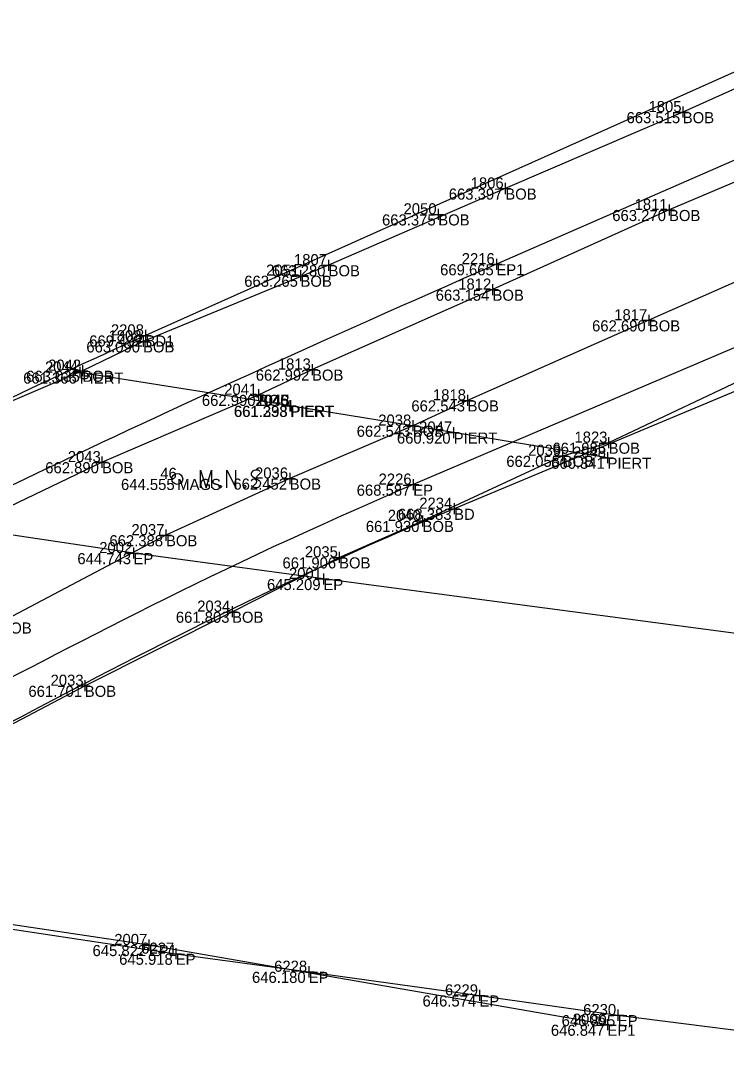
# Model space of a CAD drawing. Extents: x 2197382 to 2204062, y 634117 to 636522.
# Drawn here: x 2202884.1 to 2202947.7, y 635326 to 635420.1 of the extents above; entities that cross this region are included whole.
import ezdxf

# ---------------------------------------------------------------- set-up
doc = ezdxf.new("R2010")
doc.units = 0
for name, color, linetype in [('_CIVIL_CONSTRUCTION', 7, 'Continuous'), ('BR_X_SV_Bottom_of_Beam', 7, 'Continuous'), ('BR_X_SV_Bottom_of_Beam_Text', 7, 'Continuous'), ('BR_X_SV_Deck_Top', 7, 'Continuous'), ('BR_X_SV_Deck_Top_Text', 7, 'Continuous'), ('BR_X_SV_Pier', 7, 'Continuous'), ('BR_X_SV_Pier_Cap_Top_Text', 7, 'Continuous'), ('GE_P_Alignment_100_Distances', 7, 'Continuous'), ('SH_Border', 7, 'Continuous'), ('SH_Cut_Line', 7, 'Continuous'), ('SH_Data', 7, 'Continuous'), ('SV_P_Control_Cells_Set', 7, 'Continuous')]:
    doc.layers.add(name, color=color, linetype=linetype)

msp = doc.modelspace()

# ---------------------------------------------------------------- linework, layer by layer
at = {"layer": '_CIVIL_CONSTRUCTION'}
for p, q in [((2202943.796, 635412.429), (2202943.796, 635411.429)), ((2202943.296, 635411.929), (2202944.296, 635411.929)), ((2202943.796, 635411.929), (2202943.796, 635411.929)), ((2202927.298, 635405.044), (2202928.298, 635405.044)), ((2202927.798, 635405.544), (2202927.798, 635404.544)), ((2202927.798, 635405.044), (2202927.798, 635405.044)), ((2202921.756, 635403.216), (2202921.756, 635402.216)), ((2202942.056, 635403.113), (2202943.056, 635403.113)), ((2202942.556, 635403.613), (2202942.556, 635402.613)), ((2202942.556, 635403.113), (2202942.556, 635403.113)), ((2202921.256, 635402.716), (2202922.256, 635402.716)), ((2202921.756, 635402.716), (2202921.756, 635402.716)), ((2202911.366, 635398.135), (2202912.366, 635398.135)), ((2202911.866, 635398.635), (2202911.866, 635397.635)), ((2202911.866, 635398.135), (2202911.866, 635398.135)), ((2202926.493, 635398.223), (2202927.493, 635398.223)), ((2202926.993, 635398.723), (2202926.993, 635397.723)), ((2202926.993, 635398.223), (2202926.993, 635398.223)), ((2202908.837, 635397.193), (2202909.837, 635397.193)), ((2202909.337, 635397.693), (2202909.337, 635396.693)), ((2202909.337, 635397.193), (2202909.337, 635397.193)), ((2202926.646, 635396.436), (2202926.646, 635395.436)), ((2202926.146, 635395.936), (2202927.146, 635395.936)), ((2202926.646, 635395.936), (2202926.646, 635395.936)), ((2202940.734, 635393.673), (2202940.734, 635392.673)), ((2202940.234, 635393.173), (2202941.234, 635393.173)), ((2202940.734, 635393.173), (2202940.734, 635393.173)), ((2202894.865, 635391.811), (2202895.865, 635391.811)), ((2202895.149, 635391.777), (2202895.149, 635390.777)), ((2202895.365, 635392.311), (2202895.365, 635391.311)), ((2202895.365, 635391.811), (2202895.365, 635391.811)), ((2202894.649, 635391.277), (2202895.649, 635391.277)), ((2202895.149, 635391.277), (2202895.149, 635391.277)), ((2202889.444, 635388.969), (2202889.444, 635387.969)), ((2202889.677, 635389.132), (2202889.677, 635388.132)), ((2202909.877, 635388.736), (2202910.877, 635388.736)), ((2202910.377, 635389.236), (2202910.377, 635388.236)), ((2202910.377, 635388.736), (2202910.377, 635388.736)), ((2202888.944, 635388.469), (2202889.944, 635388.469)), ((2202889.177, 635388.632), (2202890.177, 635388.632)), ((2202889.444, 635388.469), (2202889.444, 635388.469)), ((2202889.677, 635388.632), (2202889.677, 635388.632)), ((2202905.562, 635386.959), (2202905.562, 635385.959)), ((2202905.062, 635386.459), (2202906.062, 635386.459)), ((2202905.562, 635386.459), (2202905.562, 635386.459)), ((2202908.389, 635385.967), (2202908.389, 635384.967)), ((2202908.45, 635385.97), (2202908.45, 635384.97)), ((2202923.895, 635385.96), (2202924.895, 635385.96)), ((2202924.395, 635386.46), (2202924.395, 635385.46)), ((2202924.395, 635385.96), (2202924.395, 635385.96)), ((2202907.889, 635385.467), (2202908.889, 635385.467)), ((2202907.95, 635385.47), (2202908.95, 635385.47)), ((2202908.389, 635385.467), (2202908.389, 635385.467)), ((2202908.45, 635385.47), (2202908.45, 635385.47)), ((2202919.465, 635384.18), (2202919.465, 635383.18)), ((2202918.965, 635383.68), (2202919.965, 635383.68)), ((2202919.465, 635383.68), (2202919.465, 635383.68)), ((2202922.642, 635383.059), (2202923.642, 635383.059)), ((2202923.142, 635383.559), (2202923.142, 635382.559)), ((2202923.142, 635383.059), (2202923.142, 635383.059)), ((2202936.614, 635382.149), (2202937.614, 635382.149)), ((2202937.114, 635382.649), (2202937.114, 635381.649)), ((2202937.114, 635382.149), (2202937.114, 635382.149)), ((2202932.959, 635381.469), (2202932.959, 635380.469)), ((2202937.013, 635381.295), (2202937.013, 635380.295)), ((2202890.944, 635380.393), (2202891.944, 635380.393)), ((2202891.444, 635380.893), (2202891.444, 635379.893)), ((2202891.444, 635380.393), (2202891.444, 635380.393)), ((2202932.459, 635380.969), (2202933.459, 635380.969)), ((2202932.959, 635380.969), (2202932.959, 635380.969)), ((2202936.513, 635380.795), (2202937.513, 635380.795)), ((2202937.013, 635380.795), (2202937.013, 635380.795)), ((2202908.362, 635379.417), (2202908.362, 635378.417)), ((2202907.862, 635378.917), (2202908.862, 635378.917)), ((2202908.362, 635378.917), (2202908.362, 635378.917)), ((2202918.999, 635378.368), (2202919.999, 635378.368)), ((2202919.499, 635378.868), (2202919.499, 635377.868)), ((2202919.499, 635378.368), (2202919.499, 635378.368)), ((2202923.181, 635376.697), (2202923.181, 635375.697)), ((2202920.337, 635375.601), (2202920.337, 635374.601)), ((2202922.681, 635376.197), (2202923.681, 635376.197)), ((2202923.181, 635376.197), (2202923.181, 635376.197)), ((2202919.837, 635375.101), (2202920.837, 635375.101)), ((2202920.337, 635375.101), (2202920.337, 635375.101)), ((2202896.713, 635373.813), (2202897.713, 635373.813)), ((2202897.213, 635374.313), (2202897.213, 635373.313)), ((2202897.213, 635373.813), (2202897.213, 635373.813)), ((2202894.289, 635372.701), (2202894.289, 635371.701)), ((2202893.789, 635372.201), (2202894.789, 635372.201)), ((2202894.289, 635372.201), (2202894.289, 635372.201)), ((2202912.318, 635371.819), (2202913.318, 635371.819)), ((2202912.818, 635372.319), (2202912.818, 635371.319)), ((2202912.818, 635371.819), (2202912.818, 635371.819)), ((2202910.898, 635369.868), (2202911.898, 635369.868)), ((2202911.398, 635370.368), (2202911.398, 635369.368)), ((2202911.398, 635369.868), (2202911.398, 635369.868)), ((2202903.168, 635367.423), (2202903.168, 635366.423)), ((2202902.668, 635366.923), (2202903.668, 635366.923)), ((2202903.168, 635366.923), (2202903.168, 635366.923)), ((2202889.893, 635360.75), (2202889.893, 635359.75)), ((2202889.393, 635360.25), (2202890.393, 635360.25)), ((2202889.893, 635360.25), (2202889.893, 635360.25)), ((2202895.165, 635336.892), (2202896.165, 635336.892)), ((2202895.665, 635337.392), (2202895.665, 635336.392)), ((2202895.665, 635336.892), (2202895.665, 635336.892)), ((2202897.589, 635336.111), (2202898.589, 635336.111)), ((2202898.089, 635336.611), (2202898.089, 635335.611)), ((2202898.089, 635336.111), (2202898.089, 635336.111)), ((2202909.58, 635334.482), (2202910.58, 635334.482)), ((2202910.08, 635334.982), (2202910.08, 635333.982)), ((2202910.08, 635334.482), (2202910.08, 635334.482)), ((2202924.962, 635332.351), (2202925.962, 635332.351)), ((2202925.462, 635332.851), (2202925.462, 635331.851)), ((2202925.462, 635332.351), (2202925.462, 635332.351)), ((2202937.445, 635330.578), (2202938.445, 635330.578)), ((2202937.945, 635331.078), (2202937.945, 635330.078)), ((2202937.945, 635330.578), (2202937.945, 635330.578)), ((2202936.502, 635329.713), (2202937.502, 635329.713)), ((2202937.002, 635330.213), (2202937.002, 635329.213)), ((2202937.002, 635329.713), (2202937.002, 635329.713))]:
    msp.add_line(p, q, dxfattribs=at)
at = {"layer": 'BR_X_SV_Bottom_of_Beam'}
for points in [[(2202959.784, 635419.106), (2202943.796, 635411.929), (2202927.798, 635405.044), (2202911.866, 635398.135), (2202895.149, 635391.277)], [(2202974.684, 635416.787), (2202958.622, 635409.903), (2202942.556, 635403.113), (2202926.646, 635395.936), (2202910.377, 635388.736)], [(2202989.496, 635414.407), (2202973.131, 635407.464), (2202956.928, 635400.331), (2202940.734, 635393.173), (2202924.395, 635385.96)], [(2203004.554, 635411.814), (2202987.707, 635404.283), (2202970.923, 635396.976), (2202953.857, 635390.063), (2202937.114, 635382.149)], [(2202895.149, 635391.277), (2202889.677, 635388.632), (2202873.474, 635381.691), (2202859.286, 635374.249), (2202835.616, 635361.144), (2202806.729, 635344.852)], [(2202811.504, 635338.061), (2202842.656, 635354.754), (2202862.206, 635365.361), (2202877.818, 635373.889), (2202891.444, 635380.393), (2202905.562, 635386.459), (2202910.377, 635388.736)], [(2202924.395, 635385.96), (2202919.465, 635383.68), (2202908.362, 635378.917), (2202897.213, 635373.813), (2202882.287, 635365.95), (2202883.082, 635366.661), (2202867.606, 635358.164), (2202848.789, 635348.333), (2202824.632, 635335.716)], [(2202839.929, 635334.58), (2202853.649, 635341.682), (2202872.681, 635351.202), (2202889.893, 635360.25), (2202903.168, 635366.923), (2202912.818, 635371.819), (2202920.337, 635375.101), (2202932.959, 635380.969), (2202937.114, 635382.149)]]:
    msp.add_lwpolyline(points, dxfattribs=at)
at = {"layer": 'BR_X_SV_Deck_Top'}
for p, q in [((2202958.764, 635420.145), (2202895.365, 635391.811)), ((2202999.742, 635408.201), (2202923.181, 635376.197))]:
    msp.add_line(p, q, dxfattribs=at)
for points in [[(2202895.365, 635391.811), (2202885.347, 635387.334), (2202865.192, 635377.205), (2202839.037, 635363.762), (2202813.103, 635349.723), (2202789.18, 635336.138), (2202762.388, 635320.287), (2202740.668, 635306.565), (2202716.628, 635290.831), (2202693.394, 635275.343), (2202664.567, 635254.787), (2202633.536, 635231.765), (2202595.89, 635201.643), (2202569.397, 635178.622), (2202555.165, 635165.675)], [(2202923.181, 635376.197), (2202906.167, 635369.085), (2202881.487, 635355.934), (2202846.739, 635338.13), (2202819.013, 635322.649), (2202790.142, 635306.09), (2202754.022, 635283.778), (2202709.422, 635255.583), (2202663.285, 635220.884), (2202620.566, 635187.914), (2202595.285, 635167.396), (2202582.509, 635156.81)]]:
    msp.add_open_spline(points, degree=3, dxfattribs=at)
at = {"layer": 'BR_X_SV_Pier'}
msp.add_lwpolyline([(2202937.013, 635380.795), (2202923.142, 635383.059), (2202908.389, 635385.467), (2202908.45, 635385.47), (2202889.444, 635388.469)], dxfattribs=at)
at = {"layer": 'GE_P_Alignment_100_Distances'}
for p, q in [((2202962.136, 635413.559), (2202926.993, 635398.223)), ((2202973.99, 635401.58), (2202919.499, 635378.368))]:
    msp.add_line(p, q, dxfattribs=at)
for points in [[(2202975.789, 635361.358), (2202911.398, 635369.868), (2202894.289, 635372.201), (2202871.103, 635375.635), (2202823.555, 635383.286), (2202728.393, 635399.878)], [(2202937.002, 635329.713), (2202895.665, 635336.892), (2202867.163, 635341.147), (2202804.916, 635353.945)], [(2202818.285, 635348.253), (2202834.346, 635345.79), (2202851.873, 635343.042), (2202869.038, 635340.506), (2202882.147, 635338.503), (2202898.089, 635336.111), (2202910.08, 635334.482), (2202925.462, 635332.351), (2202937.945, 635330.578), (2202955.924, 635328.277)]]:
    msp.add_lwpolyline(points, dxfattribs=at)
for points in [[(2202926.993, 635398.223), (2202911.054, 635391.267), (2202884.78, 635379.221), (2202850.251, 635362.173), (2202828.215, 635350.038), (2202808.09, 635339.198), (2202790.855, 635329.045), (2202764, 635313.325), (2202738.781, 635297.635), (2202713.051, 635280.577), (2202697.019, 635269.602), (2202684.529, 635260.864), (2202668.986, 635249.754), (2202642.65, 635230.806), (2202596.561, 635193.887), (2202560.681, 635163.156), (2202538.312, 635142.813)], [(2202919.499, 635378.368), (2202901.447, 635370.678), (2202875.936, 635356.879), (2202844.592, 635341.598), (2202825.856, 635330.823), (2202809.466, 635322.019), (2202780.051, 635304.409), (2202746.062, 635282.999), (2202707.717, 635258.176), (2202682.244, 635240.209), (2202658.947, 635222.257), (2202614.143, 635189.251), (2202577.354, 635157.516), (2202549.508, 635131.427)]]:
    msp.add_open_spline(points, degree=3, dxfattribs=at)
at = {"layer": 'SV_P_Control_Cells_Set'}
for points in [[(2202900.318, 635378.084), (2202900.318, 635379.684), (2202900.825, 635378.084), (2202901.31, 635379.684), (2202901.31, 635378.084)], [(2202900.318, 635378.084), (2202900.318, 635379.684), (2202900.825, 635378.084), (2202901.31, 635379.684), (2202901.31, 635378.084)], [(2202902.688, 635378.084), (2202902.688, 635379.684), (2202903.515, 635378.084), (2202903.515, 635379.684)], [(2202902.688, 635378.084), (2202902.688, 635379.684), (2202903.515, 635378.084), (2202903.515, 635379.684)], [(2202905.665, 635379.571), (2202905.643, 635379.596), (2202905.609, 635379.621), (2202905.51, 635379.659), (2202905.389, 635379.684), (2202905.301, 635379.684), (2202905.268, 635379.684), (2202905.124, 635379.647), (2202905.003, 635379.571), (2202904.926, 635379.47), (2202904.904, 635379.369), (2202904.904, 635379.294), (2202904.926, 635379.193), (2202905.014, 635379.105), (2202905.621, 635378.727), (2202905.676, 635378.677), (2202905.698, 635378.626), (2202905.72, 635378.551), (2202905.72, 635378.475), (2202905.709, 635378.399), (2202905.698, 635378.349), (2202905.676, 635378.286), (2202905.654, 635378.236), (2202905.631, 635378.198), (2202905.598, 635378.16), (2202905.565, 635378.135), (2202905.521, 635378.11), (2202905.488, 635378.097), (2202905.389, 635378.084), (2202905.235, 635378.084), (2202905.136, 635378.11), (2202904.992, 635378.198), (2202904.904, 635378.273)], [(2202905.665, 635379.571), (2202905.643, 635379.596), (2202905.609, 635379.621), (2202905.51, 635379.659), (2202905.389, 635379.684), (2202905.301, 635379.684), (2202905.268, 635379.684), (2202905.124, 635379.647), (2202905.003, 635379.571), (2202904.926, 635379.47), (2202904.904, 635379.369), (2202904.904, 635379.294), (2202904.926, 635379.193), (2202905.014, 635379.105), (2202905.621, 635378.727), (2202905.676, 635378.677), (2202905.698, 635378.626), (2202905.72, 635378.551), (2202905.72, 635378.475), (2202905.709, 635378.399), (2202905.698, 635378.349), (2202905.676, 635378.286), (2202905.654, 635378.236), (2202905.631, 635378.198), (2202905.598, 635378.16), (2202905.565, 635378.135), (2202905.521, 635378.11), (2202905.488, 635378.097), (2202905.389, 635378.084), (2202905.235, 635378.084), (2202905.136, 635378.11), (2202904.992, 635378.198), (2202904.904, 635378.273)], [(2202902.082, 635378.299), (2202902.137, 635378.299), (2202902.17, 635378.273), (2202902.203, 635378.223), (2202902.203, 635378.16), (2202902.17, 635378.11), (2202902.137, 635378.084), (2202902.082, 635378.084), (2202902.049, 635378.11), (2202902.016, 635378.16), (2202902.016, 635378.223), (2202902.049, 635378.273), (2202902.082, 635378.299)], [(2202902.082, 635378.299), (2202902.137, 635378.299), (2202902.17, 635378.273), (2202902.203, 635378.223), (2202902.203, 635378.16), (2202902.17, 635378.11), (2202902.137, 635378.084), (2202902.082, 635378.084), (2202902.049, 635378.11), (2202902.016, 635378.16), (2202902.016, 635378.223), (2202902.049, 635378.273), (2202902.082, 635378.299)], [(2202904.298, 635378.299), (2202904.353, 635378.299), (2202904.386, 635378.273), (2202904.419, 635378.223), (2202904.419, 635378.16), (2202904.386, 635378.11), (2202904.353, 635378.084), (2202904.298, 635378.084), (2202904.265, 635378.11), (2202904.232, 635378.16), (2202904.232, 635378.223), (2202904.265, 635378.273), (2202904.298, 635378.299)], [(2202904.298, 635378.299), (2202904.353, 635378.299), (2202904.386, 635378.273), (2202904.419, 635378.223), (2202904.419, 635378.16), (2202904.386, 635378.11), (2202904.353, 635378.084), (2202904.298, 635378.084), (2202904.265, 635378.11), (2202904.232, 635378.16), (2202904.232, 635378.223), (2202904.265, 635378.273), (2202904.298, 635378.299)], [(2202906.48, 635378.299), (2202906.535, 635378.299), (2202906.569, 635378.273), (2202906.601, 635378.223), (2202906.601, 635378.16), (2202906.569, 635378.11), (2202906.535, 635378.084), (2202906.48, 635378.084), (2202906.447, 635378.11), (2202906.414, 635378.16), (2202906.414, 635378.223), (2202906.447, 635378.273), (2202906.48, 635378.299)], [(2202906.48, 635378.299), (2202906.535, 635378.299), (2202906.569, 635378.273), (2202906.601, 635378.223), (2202906.601, 635378.16), (2202906.569, 635378.11), (2202906.535, 635378.084), (2202906.48, 635378.084), (2202906.447, 635378.11), (2202906.414, 635378.16), (2202906.414, 635378.223), (2202906.447, 635378.273), (2202906.48, 635378.299)]]:
    msp.add_lwpolyline(points, dxfattribs=at)
msp.add_circle((2202898.228, 635378.884), 0.497, dxfattribs=at)
msp.add_circle((2202898.228, 635378.884), 0.497, dxfattribs=at)

# ---------------------------------------------------------------- texts
at = {"layer": 'BR_X_SV_Bottom_of_Beam_Text'}
for s, p in [('1805', (2202940.707, 635411.929)), ('663.515', (2202938.726, 635410.929)), ('BOB', (2202943.796, 635410.929)), ('1806', (2202924.675, 635405.044)), ('663.397', (2202922.702, 635404.044)), ('BOB', (2202927.798, 635404.044)), ('2050', (2202918.624, 635402.716)), ('1811', (2202939.456, 635403.113)), ('663.270', (2202937.442, 635402.113)), ('BOB', (2202942.556, 635402.113)), ('663.375', (2202916.686, 635401.716)), ('BOB', (2202921.756, 635401.716)), ('1807', (2202908.751, 635398.135)), ('2051', (2202906.237, 635397.193)), ('663.280', (2202906.752, 635397.135)), ('BOB', (2202911.866, 635397.135)), ('663.265', (2202904.267, 635396.193)), ('BOB', (2202909.337, 635396.193)), ('1812', (2202923.554, 635395.936)), ('663.154', (2202921.524, 635394.936)), ('BOB', (2202926.646, 635394.936)), ('1817', (2202937.619, 635393.173)), ('662.690', (2202935.62, 635392.173)), ('BOB', (2202940.734, 635392.173)), ('1808', (2202892.03, 635391.277)), ('663.090', (2202890.035, 635390.277)), ('BOB', (2202895.149, 635390.277)), ('2042', (2202886.585, 635388.632)), ('1813', (2202907.294, 635388.736)), ('662.992', (2202905.304, 635387.736)), ('BOB', (2202910.377, 635387.736)), ('663.035', (2202884.607, 635387.632)), ('BOB', (2202889.677, 635387.632)), ('2041', (2202902.462, 635386.459)), ('1818', (2202921.276, 635385.96)), ('662.990', (2202900.448, 635385.459)), ('BOB', (2202905.562, 635385.459)), ('662.543', (2202919.331, 635384.96)), ('BOB', (2202924.395, 635384.96)), ('2038', (2202916.346, 635383.68)), ('662.543', (2202914.401, 635382.68)), ('BOB', (2202919.465, 635382.68)), ('1823', (2202934.031, 635382.149)), ('661.985', (2202932.044, 635381.149)), ('BOB', (2202937.114, 635381.149)), ('2043', (2202888.361, 635380.393)), ('2039', (2202929.857, 635380.969)), ('662.890', (2202886.33, 635379.393)), ('BOB', (2202891.444, 635379.393)), ('662.055', (2202927.889, 635379.969)), ('BOB', (2202932.959, 635379.969)), ('2036', (2202905.239, 635378.917)), ('662.452', (2202903.289, 635377.917)), ('BOB', (2202908.362, 635377.917)), ('2040', (2202917.205, 635375.101)), ('2037', (2202894.098, 635373.813)), ('661.930', (2202915.223, 635374.101)), ('BOB', (2202920.337, 635374.101)), ('662.388', (2202892.113, 635372.813)), ('BOB', (2202897.213, 635372.813)), ('2035', (2202909.729, 635371.819)), ('661.906', (2202907.714, 635370.819)), ('BOB', (2202912.818, 635370.819)), ('2034', (2202900.027, 635366.923)), ('661.803', (2202898.104, 635365.923)), ('BOB', (2202903.168, 635365.923)), ('BOB', (2202882.287, 635364.95)), ('2033', (2202886.81, 635360.25)), ('661.701', (2202884.811, 635359.25)), ('BOB', (2202889.893, 635359.25))]:
    msp.add_text(s, height=1, dxfattribs=at).set_placement(p)
at = {"layer": 'BR_X_SV_Deck_Top_Text'}
for s, p in [('2208', (2202892.246, 635391.811)), ('669.492', (2202890.292, 635390.811)), ('BD1', (2202895.365, 635390.811)), ('2234', (2202920.04, 635376.197)), ('668.383', (2202918.117, 635375.197)), ('BD', (2202923.181, 635375.197))]:
    msp.add_text(s, height=1, dxfattribs=at).set_placement(p)
at = {"layer": 'BR_X_SV_Pier_Cap_Top_Text'}
for s, p in [('2044', (2202886.303, 635388.469)), ('661.366', (2202884.34, 635387.469)), ('PIERT', (2202889.444, 635387.469)), ('2046', (2202905.266, 635385.467)), ('2045', (2202905.361, 635385.47)), ('661.233', (2202903.325, 635384.467)), ('661.398', (2202903.35, 635384.47)), ('PIERT', (2202908.389, 635384.467)), ('PIERT', (2202908.45, 635384.47)), ('2047', (2202920.027, 635383.059)), ('660.920', (2202918.028, 635382.059)), ('PIERT', (2202923.142, 635382.059)), ('2048', (2202933.894, 635380.795)), ('660.341', (2202931.931, 635379.795)), ('PIERT', (2202937.013, 635379.795))]:
    msp.add_text(s, height=1, dxfattribs=at).set_placement(p)
at = {"layer": 'SH_Border'}
for s, p in [('EP1', (2202926.993, 635397.223)), ('MAGS', (2202898.228, 635377.885)), ('MAGS', (2202898.228, 635377.885)), ('EP', (2202919.499, 635377.368)), ('EP', (2202894.289, 635371.201)), ('EP', (2202911.398, 635368.868)), ('EP1', (2202895.665, 635335.892)), ('EP', (2202898.089, 635335.111)), ('EP', (2202910.08, 635333.482)), ('EP', (2202925.462, 635331.351)), ('EP', (2202937.945, 635329.578)), ('EP1', (2202937.002, 635328.713))]:
    msp.add_text(s, height=1, dxfattribs=at).set_placement(p)
at = {"layer": 'SH_Cut_Line'}
for s, p in [('2216', (2202923.87, 635398.223)), ('46', (2202896.701, 635378.885)), ('46', (2202896.701, 635378.885)), ('2226', (2202916.376, 635378.368)), ('2002', (2202891.197, 635372.201)), ('2001', (2202908.298, 635369.868)), ('2007', (2202892.55, 635336.892)), ('6227', (2202894.974, 635336.111)), ('6228', (2202906.961, 635334.482)), ('6229', (2202922.36, 635332.351)), ('6230', (2202934.813, 635330.578)), ('2006', (2202933.879, 635329.713))]:
    msp.add_text(s, height=1, dxfattribs=at).set_placement(p)
at = {"layer": 'SH_Data'}
for s, p in [('669.665', (2202921.923, 635397.223)), ('644.555', (2202893.158, 635377.885)), ('644.555', (2202893.158, 635377.885)), ('668.587', (2202914.403, 635377.368)), ('644.743', (2202889.225, 635371.201)), ('645.209', (2202906.314, 635368.868)), ('645.822', (2202890.592, 635335.892)), ('645.918', (2202892.989, 635335.111)), ('646.180', (2202904.966, 635333.482)), ('646.574', (2202920.34, 635331.351)), ('646.895', (2202932.875, 635329.578)), ('646.847', (2202931.906, 635328.713))]:
    msp.add_text(s, height=1, dxfattribs=at).set_placement(p)

doc.saveas('drawing.dxf')
